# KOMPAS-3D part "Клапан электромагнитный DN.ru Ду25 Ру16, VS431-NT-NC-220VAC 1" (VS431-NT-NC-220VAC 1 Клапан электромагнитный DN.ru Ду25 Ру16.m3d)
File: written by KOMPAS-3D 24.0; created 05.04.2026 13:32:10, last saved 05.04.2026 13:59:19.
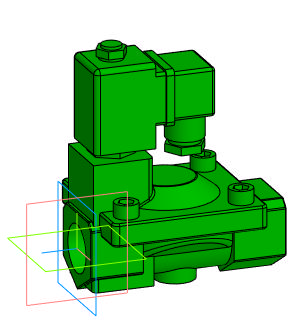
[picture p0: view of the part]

Document properties: Автор: artio; Полное имя файла: C:\Users\artio\OneDrive\Рабочий стол\Клапан электромагнитный DN.ru\VS431\VS431-NT-NC\VS431-NT-NC-220VAC\Ду25\VS431-NT-NC-220VAC 1 Клапан электромагнитный DN.ru Ду25 Ру16.m3d

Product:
- Body: Тело 1  | qty 1
    Масса: 1.729172
- Part/product: Клапан электромагнитный DN.ru Ду25 Ру16  | designation VS431-NT-NC-220VAC 1
    Масса: 1.267
    Раздел спецификации: Прочие изделия
    Примечание: D130-04670
    additional columns: ef56311e-7521-43dc-8291-0e6108b3d81d; artio; c; Шероховатость не задана; Да

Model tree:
1. Операция без истории:1

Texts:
  VS431-NT-NC-220VAC 1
